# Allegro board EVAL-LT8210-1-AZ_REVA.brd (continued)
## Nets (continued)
UNNAMED_3_ADLT82101_I10_IMON: CIMON3.1 IMON3.1(N1) R28.2(N2) RIMON3.1 U3.7
UNNAMED_3_ADLT82101_I10_RT: RT3.2(N2) U3.3
UNNAMED_3_ADLT82101_I10_SNSN1: C63.2(N2) R24.2(N2) U3.30
UNNAMED_3_ADLT82101_I10_SNSP1: C63.1 R23.2(N2) U3.31
UNNAMED_3_ADLT82101_I10_SS: CSS3.2(N2) U3.6
UNNAMED_3_ADLT82101_I10_SW1: CBST5.1 MA5.1 MA5.2 MA5.3(S3) MA6.1 MA6.2 MA6.3(S3) MB5.5 MB5.6 MB5.7 MB5.8 MB6.5 MB6.6 MB6.7 MB6.8 RSNS7.4(N4) RSNS7_1.4(N4) U3.28
UNNAMED_3_ADLT82101_I10_SW2: CBST6.2(N2) L3.2(N2) L3B.1(N1) MC5.5 MC5.6 MC5.7 MC5.8 MC6.5 MC6.6 MC6.7 MC6.8 MD5.1 MD5.2 MD5.3(S3) MD6.1 MD6.2 MD6.3(S3) U3.19
UNNAMED_3_ADLT82101_I10_TG1: MA5.4 MA6.4 TPA3.1(N1) U3.29
UNNAMED_3_ADLT82101_I10_TG2: MD5.4 MD6.4 TPD3.1(N1) U3.18
UNNAMED_3_ADLT82101_I10_VC1: CP5.2(N2) R29.2(N2) RC7.2(N2) RC9.1 U3.8
UNNAMED_3_ADLT82101_I10_VC2: CP6.2(N2) R30.1 RC8.2(N2) RC9.2(N2) U3.9
UNNAMED_3_ADLT82101_I10_VDD: CVDD3.2(N2) D5.A(P) U3.5
UNNAMED_3_ADLT82101_I10_VIN: C53.2(N2) RIN3.1 U3.35
UNNAMED_3_ADLT82101_I10_VINP: C54.2(N2) R22.1 U3.33
UNNAMED_3_ADLT82101_I10_VOUT: CFOUT3.1 ROUT3.1 U3.13(VOUT)
UNNAMED_3_CAP_I22_N1: C49.1 MDG5.4 MDG6.4 R21.1
UNNAMED_3_CAP_I128_N2: C64.2(N2) C65.2(N2) C66.2(N2) C67.2(N2) C68.2(N2) C69.2(N2) C70.P C70_1.P MD5.5 MD5.6 MD5.7 MD5.8 MD6.5 MD6.6 MD6.7 MD6.8 R26.2(N2) R66.1 ROUT3.2(N2) RSNS8.3 RSNS8.4(N4) RSNS8_1.3 RSNS8_1.4(N4)
UNNAMED_3_CAP_I151_N2: CC5.2(N2) RC7.1
UNNAMED_3_CAP_I154_N2: CC6.2(N2) RC8.1
UNNAMED_3_CAPP_I25_N1: C50.P C51.P C51_1.P C52.P C52_1.P C55.P C56.2(N2) C57.2(N2) C58.2(N2) C59.2(N2) C60.2(N2) C61.2(N2) C62.2(N2) MA5.5 MA5.6 MA5.7 MA5.8 MA6.5 MA6.6 MA6.7 MA6.8 MDG5.5 MDG5.6 MDG5.7 MDG5.8 MDG6.5 MDG6.6 MDG6.7 MDG6.8 R22.2(N2) RSNS9.2 RSNS9.4(N4) RSNS9_1.2 RSNS9_1.4(N4)
UNNAMED_3_DIOLED_I1_P: DS3.A(P) RPWGD3.1
UNNAMED_3_IND_I87_N1: L3.1 L3A.1(N1) RSNS7.2 RSNS7_1.2
UNNAMED_3_NCTESTPAD_I76_N1: MB5.4 MB6.4 RBG5.1 TPB3.1(N1)
UNNAMED_3_NCTESTPAD_I88_N1: MC5.4 MC6.4 RBG6.1 TPC3.1(N1)
UNNAMED_3_RES_I33_N2: RSNPA3.2(N2) RSNS9.3 RSNS9_1.3
UNNAMED_3_RES_I37_N2: RSNPB3.2(N2) RSNS9.1 RSNS9_1.1
UNNAMED_3_RES_I78_N1: R23.1 RSNS7.3 RSNS7_1.3
UNNAMED_3_RES_I84_N1: R24.1 RSNS7.1 RSNS7_1.1
UNNAMED_3_RES_I117_N1: R1A3.1 R1C3.1 R59.1
UNNAMED_3_RES_I120_N1: R2A3.1 R2C3.1 R60.1
UNNAMED_4_ADLT82101_I10_BG1: RBG7.2(N2) U4.23
UNNAMED_4_ADLT82101_I10_BG2: RBG8.2(N2) U4.21
UNNAMED_4_ADLT82101_I10_BST1: RBST7.2(N2) U4.27
UNNAMED_4_ADLT82101_I10_BST2: RBST8.2(N2) U4.20
UNNAMED_4_ADLT82101_I10_DG: DG4.1(N1) R31.2(N2) U4.34
UNNAMED_4_ADLT82101_I10_FB1: R1A4.2(N2) R1B4.1 R3C4.1 U4.11
UNNAMED_4_ADLT82101_I10_FB2: R2A4.2(N2) R2B4.2(N2) R3C4.2(N2) U4.10
UNNAMED_4_ADLT82101_I10_GATEVCC: CGATE4.1 DBST7.A(P) DBST8.A(P) U4.24
UNNAMED_4_ADLT82101_I10_IMON: CIMON4.1 IMON4.1(N1) R38.2(N2) RIMON4.1 U4.7
UNNAMED_4_ADLT82101_I10_RT: RT4.2(N2) U4.3
UNNAMED_4_ADLT82101_I10_SNSN1: C87.2(N2) R34.2(N2) U4.30
UNNAMED_4_ADLT82101_I10_SNSP1: C87.1 R33.2(N2) U4.31
UNNAMED_4_ADLT82101_I10_SS: CSS4.2(N2) U4.6
UNNAMED_4_ADLT82101_I10_SW1: CBST7.1 MA7.1 MA7.2 MA7.3(S3) MA8.1 MA8.2 MA8.3(S3) MB7.5 MB7.6 MB7.7 MB7.8 MB8.5 MB8.6 MB8.7 MB8.8 RSNS10.4(N4) RSNS10_1.4(N4) U4.28
UNNAMED_4_ADLT82101_I10_SW2: CBST8.2(N2) L4.2(N2) L4B.1(N1) MC7.5 MC7.6 MC7.7 MC7.8 MC8.5 MC8.6 MC8.7 MC8.8 MD7.1 MD7.2 MD7.3(S3) MD8.1 MD8.2 MD8.3(S3) U4.19
UNNAMED_4_ADLT82101_I10_TG1: MA7.4 MA8.4 TPA4.1(N1) U4.29
UNNAMED_4_ADLT82101_I10_TG2: MD7.4 MD8.4 TPD4.1(N1) U4.18
UNNAMED_4_ADLT82101_I10_VC1: CP7.2(N2) R39.2(N2) RC10.2(N2) RC12.1 U4.8
UNNAMED_4_ADLT82101_I10_VC2: CP8.2(N2) R40.1 RC11.2(N2) RC12.2(N2) U4.9
UNNAMED_4_ADLT82101_I10_VDD: CVDD4.2(N2) D7.A(P) U4.5
UNNAMED_4_ADLT82101_I10_VIN: C77.2(N2) RIN4.1 U4.35
UNNAMED_4_ADLT82101_I10_VINP: C78.2(N2) R32.1 U4.33
UNNAMED_4_ADLT82101_I10_VOUT: CFOUT4.1 ROUT4.1 U4.13(VOUT)
UNNAMED_4_CAP_I22_N1: C73.1 MDG7.4 MDG8.4 R31.1
UNNAMED_4_CAP_I128_N2: C88.2(N2) C89.2(N2) C90.2(N2) C91.2(N2) C92.2(N2) C93.2(N2) C94.P C94_1.P MD7.5 MD7.6 MD7.7 MD7.8 MD8.5 MD8.6 MD8.7 MD8.8 R36.2(N2) R67.1 ROUT4.2(N2) RSNS11.3 RSNS11.4(N4) RSNS11_1.3 RSNS11_1.4(N4)
UNNAMED_4_CAP_I151_N2: CC7.2(N2) RC10.1
UNNAMED_4_CAP_I154_N2: CC8.2(N2) RC11.1
UNNAMED_4_CAPP_I25_N1: C74.P C75.P C75_1.P C76.P C76_1.P C79.P C80.2(N2) C81.2(N2) C82.2(N2) C83.2(N2) C84.2(N2) C85.2(N2) C86.2(N2) MA7.5 MA7.6 MA7.7 MA7.8 MA8.5 MA8.6 MA8.7 MA8.8 MDG7.5 MDG7.6 MDG7.7 MDG7.8 MDG8.5 MDG8.6 MDG8.7 MDG8.8 R32.2(N2) RSNS12.2 RSNS12.4(N4) RSNS12_1.2 RSNS12_1.4(N4)
UNNAMED_4_DIOLED_I1_P: DS4.A(P) RPWGD4.1
UNNAMED_4_IND_I87_N1: L4.1 L4A.1(N1) RSNS10.2 RSNS10_1.2
UNNAMED_4_NCTESTPAD_I76_N1: MB7.4 MB8.4 RBG7.1 TPB4.1(N1)
UNNAMED_4_NCTESTPAD_I88_N1: MC7.4 MC8.4 RBG8.1 TPC4.1(N1)
UNNAMED_4_RES_I33_N2: RSNPA4.2(N2) RSNS12.3 RSNS12_1.3
UNNAMED_4_RES_I37_N2: RSNPB4.2(N2) RSNS12.1 RSNS12_1.1
UNNAMED_4_RES_I78_N1: R33.1 RSNS10.3 RSNS10_1.3
UNNAMED_4_RES_I84_N1: R34.1 RSNS10.1 RSNS10_1.1
UNNAMED_4_RES_I117_N1: R1A4.1 R1C4.1 R61.1
UNNAMED_4_RES_I120_N1: R2A4.1 R2C4.1 R62.1
UNNAMED_5_ADLT8631_I47_BST: C104.2(N2) U6.18
UNNAMED_5_ADLT8631_I47_EN: R46.2(N2) R47.1 U6.3
UNNAMED_5_ADLT8631_I47_FB: C105.2(N2) R49.2(N2) R50.1 U6.11
UNNAMED_5_ADLT8631_I47_IND: L6.1 U6.14
UNNAMED_5_ADLT8631_I47_INTVCC: C106.1 U6.16
UNNAMED_5_ADLT8631_I47_RT: R48.1 U6.8
UNNAMED_5_ADLT8631_I47_SW: C104.1 D9.C L6.2(N2) U6.20
UNNAMED_5_ADLT8631_I47_TR: C103.1 U6.10
UNNAMED_5_ADLT8631_I47_VIN: C98.P C100.1 C102.2(N2) L5.2(N2) R46.1 U6.1
UNNAMED_5_ADLT8631_I47_VOUT: C105.1 C107.1 C108.1 R49.1 R51.1 R52.1 R53.1 R54.1 U6.12(VOUT)
UNNAMED_5_ADLT8631_I98_BST: C120.2(N2) U7.18
UNNAMED_5_ADLT8631_I98_EN: R69.2(N2) R70.1 U7.3
UNNAMED_5_ADLT8631_I98_FB: C121.2(N2) R78.2(N2) R79.1 U7.11
UNNAMED_5_ADLT8631_I98_IND: L7.1 U7.14
UNNAMED_5_ADLT8631_I98_INTVCC: C122.1 U7.16
UNNAMED_5_ADLT8631_I98_RT: R71.1 U7.8
UNNAMED_5_ADLT8631_I98_SW: C120.1 D4.C L7.2(N2) U7.20
UNNAMED_5_ADLT8631_I98_TR: C118.1 U7.10
UNNAMED_5_ADLT8631_I98_VOUT: C119.1 C121.1 C123.1 C124.1 R75.1 R78.1 U7.12(VOUT) U8.4
UNNAMED_5_ADLTC2052X_I74_: R73.2(N2) R74.1 R77.1 U8.3
UNNAMED_5_ADLTC2052X_I74__1: R75.2(N2) R76.1 U8.2
UNNAMED_5_ADLTC2052X_I82_: U8.13 U8.14
UNNAMED_5_ADLTC2052X_I83_: U8.8 U8.9
UNNAMED_5_ADLTC2052X_I92_: U8.6 U8.7
UNNAMED_5_DIOMMBZ5221_I58_N: D2.3 R72.2(N2) R73.1
UNNAMED_7_ADLT82101_I136_BG1: RBG3.2(N2) U2.23
UNNAMED_7_ADLT82101_I136_BG2: RBG4.2(N2) U2.21
UNNAMED_7_ADLT82101_I136_BST1: RBST3.2(N2) U2.27
UNNAMED_7_ADLT82101_I136_BST2: RBST4.2(N2) U2.20
UNNAMED_7_ADLT82101_I136_DG: DG2.1(N1) R11.2(N2) U2.34
UNNAMED_7_ADLT82101_I136_FB1: R1A2.2(N2) R1B2.1 R3C2.1 U2.11
UNNAMED_7_ADLT82101_I136_FB2: R2A2.2(N2) R2B2.2(N2) R3C2.2(N2) U2.10
UNNAMED_7_ADLT82101_I136_GATEVCC: CGATE2.1 DBST3.A(P) DBST4.A(P) U2.24
UNNAMED_7_ADLT82101_I136_IMON: CIMON2.1 IMON2.1(N1) R18.2(N2) RIMON2.1 U2.7
UNNAMED_7_ADLT82101_I136_RT: RT2.2(N2) U2.3
UNNAMED_7_ADLT82101_I136_SNSN1: C39.2(N2) R14.2(N2) U2.30
UNNAMED_7_ADLT82101_I136_SNSP1: C39.1 R13.2(N2) U2.31
UNNAMED_7_ADLT82101_I136_SS: CSS2.2(N2) U2.6
UNNAMED_7_ADLT82101_I136_SW1: CBST3.1 MA3.1 MA3.2 MA3.3(S3) MA4.1 MA4.2 MA4.3(S3) MB3.5 MB3.6 MB3.7 MB3.8 MB4.5 MB4.6 MB4.7 MB4.8 RSNS4.4(N4) RSNS4_1.4(N4) U2.28
UNNAMED_7_ADLT82101_I136_SW2: CBST4.2(N2) L2.2(N2) L2B.1(N1) MC3.5 MC3.6 MC3.7 MC3.8 MC4.5 MC4.6 MC4.7 MC4.8 MD3.1 MD3.2 MD3.3(S3) MD4.1 MD4.2 MD4.3(S3) U2.19
UNNAMED_7_ADLT82101_I136_TG1: MA3.4 MA4.4 TPA2.1(N1) U2.29
UNNAMED_7_ADLT82101_I136_TG2: MD3.4 MD4.4 TPD2.1(N1) U2.18
UNNAMED_7_ADLT82101_I136_VC1: CP3.2(N2) R19.2(N2) RC4.2(N2) RC6.1 U2.8
UNNAMED_7_ADLT82101_I136_VC2: CP4.2(N2) R20.1 RC5.2(N2) RC6.2(N2) U2.9
UNNAMED_7_ADLT82101_I136_VDD: CVDD2.2(N2) D3.A(P) U2.5
UNNAMED_7_ADLT82101_I136_VIN: C29.2(N2) RIN2.1 U2.35
UNNAMED_7_ADLT82101_I136_VINP: C30.2(N2) R12.1 U2.33
UNNAMED_7_ADLT82101_I136_VOUT: CFOUT2.1 ROUT2.1 U2.13(VOUT)
UNNAMED_7_CAP_I21_N1: C25.1 MDG3.4 MDG4.4 R11.1
UNNAMED_7_CAP_I127_N2: C40.2(N2) C41.2(N2) C42.2(N2) C43.2(N2) C44.2(N2) C45.2(N2) C46.P C46_1.P MD3.5 MD3.6 MD3.7 MD3.8 MD4.5 MD4.6 MD4.7 MD4.8 R16.2(N2) R68.1 ROUT2.2(N2) RSNS5.3 RSNS5.4(N4) RSNS5_1.3 RSNS5_1.4(N4)
UNNAMED_7_CAP_I151_N2: CC3.2(N2) RC4.1
UNNAMED_7_CAP_I154_N2: CC4.2(N2) RC5.1
UNNAMED_7_CAPP_I24_N1: C26.P C27.P C27_1.P C28.P C28_1.P C31.P C32.2(N2) C33.2(N2) C34.2(N2) C35.2(N2) C36.2(N2) C37.2(N2) C38.2(N2) MA3.5 MA3.6 MA3.7 MA3.8 MA4.5 MA4.6 MA4.7 MA4.8 MDG3.5 MDG3.6 MDG3.7 MDG3.8 MDG4.5 MDG4.6 MDG4.7 MDG4.8 R12.2(N2) RSNS6.2 RSNS6.4(N4) RSNS6_1.2 RSNS6_1.4(N4)
UNNAMED_7_DIOLED_I1_P: DS2.A(P) RPWGD2.1
UNNAMED_7_IND_I86_N1: L2.1 L2A.1(N1) RSNS4.2 RSNS4_1.2
UNNAMED_7_NCTESTPAD_I75_N1: MB3.4 MB4.4 RBG3.1 TPB2.1(N1)
UNNAMED_7_NCTESTPAD_I87_N1: MC3.4 MC4.4 RBG4.1 TPC2.1(N1)
UNNAMED_7_RES_I32_N2: RSNPA2.2(N2) RSNS6.3 RSNS6_1.3
UNNAMED_7_RES_I36_N2: RSNPB2.2(N2) RSNS6.1 RSNS6_1.1
UNNAMED_7_RES_I77_N1: R13.1 RSNS4.3 RSNS4_1.3
UNNAMED_7_RES_I83_N1: R14.1 RSNS4.1 RSNS4_1.1
UNNAMED_7_RES_I116_N1: R1A2.1 R1C2.1 R63.1
UNNAMED_7_RES_I119_N1: R2A2.1 R2C2.1 R64.1
VC1: R9.1 R19.1 R29.1 R39.1
VC2: R10.2(N2) R20.2(N2) R30.2(N2) R40.2(N2)
VOUT: C23.P C23_1.P C47.P C47_1.P C71.P C71_1.P C95.P C95_1.P C109.2(N2) C110.2(N2) C111.2(N2) C112.2(N2) C113.2(N2) C114.2(N2) C115.2(N2) C116.2(N2) E4.1(N1) P7.1(N1) P8.1(N1) R1C1.2(N2) R1C2.2(N2) R1C3.2(N2) R1C4.2(N2) R2C1.2(N2) R2C2.2(N2) R2C3.2(N2) R2C4.2(N2) R5.1 R7.2(N2) R15.1 R17.2(N2) R25.1 R27.2(N2) R35.1 R37.2(N2) R57.1 R58.1 R65.2(N2) R66.2(N2) R67.2(N2) R68.2(N2) RSNS2.1 RSNS2.2 RSNS2_1.1 RSNS2_1.2 RSNS5.1 RSNS5.2 RSNS5_1.1 RSNS5_1.2 RSNS8.1 RSNS8.2 RSNS8_1.1 RSNS8_1.2 RSNS11.1 RSNS11.2 RSNS11_1.1 RSNS11_1.2

Pads without a net: D2 2; U1 12 14 17 26 32 36 38; U2 12 14 17 26 32 36 38; U3 12 14 17 26 32 36 38; U4 12 14 17 26 32 36 38; U5 2; U6 5 6 9 13 15; U7 5 6 9 13 15

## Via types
v1: diameter 0.508, hole 0.254, TOP to BOTTOM, 228 vias
v2: diameter 0.61, hole 0.305, TOP to BOTTOM, 6707 vias
v3: diameter 0.61, hole 0.254, TOP to BOTTOM, 100 vias

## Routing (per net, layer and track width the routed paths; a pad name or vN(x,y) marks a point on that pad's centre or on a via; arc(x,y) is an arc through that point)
GND_POWER: length 32.2
  TOP w0.203: C2.N v2(47.5,33.15)
  TOP w0.254: U4.4 113.43,285.62 v1(113.26,285.44) ; v1(113.26,195.66) 113.43,195.83 U3.4 ; U2.4 113.44,106.04 v1(113.26,105.87) ; v1(113.26,18.62) 113.43,18.79 U1.4
  TOP w0.279: RIMON1.2 110.39,12.66 CIMON1.2 111.8,12.6 111.8,9.98 ; U4.22 115.93,294.08 v2(116.64,294.78) ; v2(116.64,115.2) 115.94,114.5 U2.22 ; v2(116.64,204.99) 115.93,204.29 U3.22 ; 111.8,276.81 111.8,279.43 CIMON4.2 110.39,279.49 RIMON4.2 ; 107.75,277.91 107.91,277.75 ; v2(116.64,27.95) 115.93,27.25 U1.22
  TOP w0.305: C106.2 84.07,101.93 83.64,102.36 v1(83.57,102.36)
  TOP w0.381: U7.7 78.83,175.81 v2(78.61,176.02) v2(77.85,176.78)
  vias: v1(49.2,280.81) v1(78.38,284.63) v1(83.85,284.63) v1(100.08,100.2) v1(102.32,282.03) v1(102.32,192.24) v1(102.32,15.2) v1(107.72,15.75) v2(7.44,197.36) v2(7.43,174.43) v2(7.87,199.81) v2(7.87,194.91) v2(7.86,176.88) v2(7.86,171.98) v2(9.12,201.96) v2(9.12,192.75) v2(9.11,179.04) v2(9.11,169.83) v2(11.02,203.56) v2(11.02,191.15) v2(11.01,180.64) v2(11.01,168.23) v2(13.13,160.15) v2(13.11,157.1) v2(13.36,204.41) v2(13.36,190.3) v2(13.35,181.49) v2(13.35,167.38) v2(14.17,160.15) v2(14.15,157.1) v2(15.19,160.15) v2(15.16,157.1) v2(15.85,204.41) v2(15.85,190.3) v2(15.84,181.49) v2(15.84,167.38) v2(16.28,160.15) v2(16.26,157.1) v2(18.19,203.56) v2(18.19,191.15) v2(18.17,180.64) v2(18.17,168.23) v2(20.09,201.96) v2(20.09,192.75) v2(20.08,179.04) v2(20.08,169.83) v2(21.34,199.81) v2(21.34,194.91) v2(21.32,176.88) v2(21.32,171.98) v2(21.77,197.36) v2(21.76,174.43) v2(32.98,354.45) v2(32.98,351.91) v2(32.98,349.37) v2(32.98,346.83) v2(32.98,344.29) v2(32.93,38.72) v2(33.13,304.06) v2(33.13,298.98) v2(33.13,296.44) v2(33.13,293.9) v2(33.13,291.36) v2(33.13,288.82) v2(33.13,276.12) v2(33.13,273.58) v2(33.13,271.04) v2(33.13,265.96) v2(33.13,263.42) v2(33.13,260.88) v2(33.13,258.34) v2(33.13,255.8) v2(33.13,253.26) v2(33.15,217.81) v2(33.13,214.27) v2(33.13,209.19) v2(33.13,206.65) v2(33.13,204.11) v2(33.13,201.57) v2(33.13,199.03) v2(33.13,196.49) v2(33.13,193.95) v2(33.13,191.41) v2(33.13,188.87) v2(33.13,186.33) v2(33.13,183.79) v2(33.13,181.25) v2(33.13,171.09) v2(33.13,168.55) v2(33.13,166.01) v2(33.13,163.47) v2(33.13,124.48) v2(33.13,119.4) v2(33.13,116.86) v2(33.13,114.32) v2(33.13,111.78) v2(33.13,109.24) v2(33.13,106.7) v2(33.13,104.16) v2(33.13,101.62) v2(33.13,99.08) v2(33.13,96.54) v2(33.13,94) v2(33.13,86.38) v2(33.13,83.84) v2(33.13,81.3) v2(33.13,78.76) v2(33.13,76.22) v2(33.13,35.56) v2(33.13,33.02) v2(33.13,30.48) v2(33.13,27.94) v2(33.13,25.4) v2(33.13,22.86) v2(33.13,20.32) v2(33.13,17.78) v2(33.13,15.24) v2(33.13,12.7) v2(33.13,10.16) v2(33.13,7.62) v2(33.13,5.08) v2(34.16,171.7) v2(34.29,82.42) v2(34.32,356.23) v2(34.46,342.82) v2(34.8,351.79) v2(34.8,346.71) v2(34.8,86.11) v2(35.18,297.56) v2(35.18,272.16) v2(35.18,262) v2(35.18,256.92) v2(35.17,217.93) v2(35.18,212.85) v2(35.18,207.77) v2(35.18,202.69) v2(35.18,197.61) v2(35.18,192.53) v2(35.18,187.45) v2(35.18,182.37) v2(35.18,167.13) v2(35.18,120.52) v2(35.18,119) v2(35.18,115.44) v2(35.18,110.36) v2(35.17,40.83) v2(35.18,35.56) v2(35.18,30.48) v2(35.18,25.4) v2(35.18,20.32) v2(35.18,15.24) v2(35.18,10.16) v2(35.18,5.08) v2(35.18,2.92) v2(35.31,195.12) v2(35.38,163.25) v2(35.41,253.05) v2(35.4,76.01) v2(35.59,190.12) v2(36.52,216.61) v2(36.53,208.99) v2(36.53,203.91) v2(36.53,198.83) v2(36.86,356.23) v2(37,342.82) v2(37.34,354.33) v2(37.35,215.44) v2(37.34,125.73) v2(37.69,163.32) v2(37.71,307.72) v2(37.72,300.1) v2(37.72,295.02) v2(37.72,270) v2(37.72,264.92) v2(37.72,184.91) v2(37.72,179.83) v2(37.72,117.98) v2(37.72,112.9) v2(37.72,107.82) v2(37.71,40.83) v2(37.72,35.56) v2(37.72,33.02) v2(37.72,27.94) v2(37.72,22.86) v2(37.72,17.78) v2(37.72,12.7) v2(37.72,7.62) v2(37.72,2.92) v2(37.92,347.34) v2(37.92,256.92) v2(37.92,168.97) v2(37.93,81.72) v2(39.17,285.24) v2(39.4,356.23) v2(39.45,283.03) v2(39.54,342.82) v2(39.62,346.71) v2(39.8,266.18) v2(39.78,253.42) v2(39.78,217.67) v2(39.8,215.36) v2(39.8,212.74) v2(39.79,210.43) v2(39.8,191.51) v2(39.78,100.85) v2(39.88,351.79) v2(39.81,268.98) v2(39.83,179.18) v2(39.81,167.12) v2(39.83,125.09) v2(39.83,120.52) v2(40.14,40.86) v2(40.25,307.72) v2(40.26,297.56) v2(40.26,10.16) v2(40.26,5.08) v2(40.26,2.92) v2(41.73,283.08) v2(41.71,256.13) v2(41.73,253.05) v2(41.78,86.74) v2(41.83,261.26) v2(41.94,356.23) v2(41.91,84.96) v2(41.91,79.88) v2(42.08,342.82) v2(42.42,354.33) v2(42.42,349.25) v2(42.42,344.17) v2(42.79,307.72) v2(42.8,305.18) v2(42.8,295.02) v2(42.8,7.62) v2(42.8,2.92) v2(43.57,40.82) v2(43.82,171.58) v2(43.95,274.96) v2(43.95,270.84) v2(43.95,264.31) v2(44.48,356.23) v2(44.62,342.82) v2(44.96,351.79) v2(44.96,346.71) v2(45.33,307.72) v2(45.34,302.64) v2(45.34,297.56) v2(45.34,262) v2(45.34,256.92) v2(45.33,217.93) v2(45.34,207.77) v2(45.34,202.69) v2(45.34,197.61) v2(45.34,187.45) v2(45.34,182.37) v2(45.34,167.13) v2(45.34,125.6) v2(45.34,115.95) v2(45.34,110.36) v2(45.34,95.12) v2(45.34,5.08) v2(45.34,2.92) v2(45.42,253.06) v2(45.43,163.26) v2(45.44,76.01) v2(46.96,304.24) v2(46.99,84.96) v2(46.99,79.88) v2(47.02,356.23) v2(47.16,342.82) v2(47.5,354.33) v2(47.5,349.25) v2(47.5,344.17) v2(47.5,213.74) v2(47.53,123.08) v2(47.54,40.82) v2(47.62,86.11) v2(47.87,307.72) v2(47.88,295.02) v2(47.88,205.61) v2(47.88,184.91) v2(47.88,179.83) v2(47.88,169.67) v2(47.88,163.2) v2(47.88,117.98) v2(47.88,103) v2(47.88,97.66) v2(47.88,2.92) v2(48.39,171.58) v2(49.15,212.85) v2(49.4,262) v2(49.4,257.05) v2(49.42,253.05) v2(49.4,207.52) v2(49.4,187.45) v2(49.4,182.37) v2(49.4,125.6) v2(49.4,115.95) v2(49.56,356.23) v2(49.53,217.82) v2(49.53,167.26) v2(49.53,82.42) v2(49.53,77.34) v2(49.7,342.82) v2(50.04,351.79) v2(50.04,346.71) v2(50.01,25.3) v2(50.41,307.72) v2(50.42,302.64) v2(50.42,297.56) v2(50.42,2.92) v2(50.9,95.22) v2(50.9,40.83) v2(51.94,25.6) v2(52.1,356.23) v2(52.24,342.82) v2(52.58,354.33) v2(52.58,349.25) v2(52.58,344.17) v2(52.95,307.72) v2(52.96,305.18) v2(52.96,295.02) v2(52.96,269.62) v2(52.96,205.23) v2(52.96,200.15) v2(52.96,2.92) v2(53.19,253.05) v2(53.34,103) v2(53.59,217.68) v2(53.59,215.39) v2(53.72,164.34) v2(53.98,122.94) v2(54.1,185.04) v2(54.1,179.96) v2(54.1,79.76) v2(54.36,117.86) v2(54.36,112.78) v2(54.36,107.7) v2(54.48,264.54) v2(54.64,356.23) v2(54.78,342.82) v2(54.74,86.49) v2(55.42,308.31) v2(55.5,302.64) v2(55.5,297.56) v2(55.42,218.52) v2(55.5,212.85) v2(55.5,207.77) v2(55.5,202.69) v2(55.5,197.61) v2(55.5,130.68) v2(55.42,128.73) v2(55.5,125.6) v2(55.5,115.95) v2(55.5,110.36) v2(55.5,95.12) v2(55.42,41.48) v2(55.5,40.64) v2(55.5,35.56) v2(55.5,15.24) v2(55.5,10.16) v2(55.5,2.92) v2(55.72,76.01) v2(55.8,347.28) v2(55.8,256.8) v2(55.8,168.84) v2(55.8,81.59) v2(57.18,356.23) v2(57.32,342.82) v2(57.66,354.33) v2(57.66,349.25) v2(57.66,344.17) v2(58.04,310.26) v2(58.04,305.18) v2(58.04,295.02) v2(58.04,269.62) v2(58.04,264.54) v2(58.04,259.46) v2(58.04,254.38) v2(58.04,220.47) v2(58.04,215.39) v2(58.04,205.23) v2(58.04,200.15) v2(58.04,184.91) v2(58.04,179.83) v2(58.04,169.67) v2(58.04,164.59) v2(58.04,128.14) v2(58.04,123.06) v2(58.04,117.98) v2(58.04,112.9) v2(58.04,107.82) v2(58.04,97.66) v2(58.04,43.18) v2(58.04,33.02) v2(58.04,27.94) v2(58.04,2.92) v2(58.17,103) v2(58.27,253.05) v2(58.25,163.27) v2(58.26,76.01) v2(59.31,93.73) v2(59.56,171.7) v2(59.69,82.42) v2(59.72,356.23) v2(59.86,342.82) v2(60.2,351.79) v2(60.2,346.71) v2(60.19,340.12) v2(60.19,337.58) v2(60.19,335.04) v2(60.19,332.5) v2(60.19,329.96) v2(60.33,251.16) v2(60.33,248.62) v2(60.33,246.08) v2(60.33,243.54) v2(60.33,241) v2(60.31,161.37) v2(60.31,158.83) v2(60.31,156.29) v2(60.31,153.75) v2(60.31,151.21) v2(60.31,74.12) v2(60.31,71.58) v2(60.31,69.04) v2(60.31,66.5) v2(60.31,63.96) v2(60.58,302.64) v2(60.58,297.56) v2(60.58,272.16) v2(60.58,262) v2(60.58,256.92) v2(60.58,212.85) v2(60.58,207.77) v2(60.58,202.69) v2(60.58,197.61) v2(60.58,187.45) v2(60.58,182.37) v2(60.58,167.13) v2(60.58,115.95) v2(60.58,110.36) v2(60.58,35.56) v2(60.58,30.48) v2(60.58,25.4) v2(60.58,20.32) v2(60.58,10.16) v2(60.58,2.92) v2(60.71,86.36) v2(62.19,149.91) v2(62.26,356.23) v2(62.24,239.76) v2(62.23,79.88) v2(62.23,74.8) v2(62.23,69.72) v2(62.22,62.66) v2(62.62,329.64) v2(62.74,354.33) v2(62.74,349.25) v2(62.74,344.17) v2(62.74,339.09) v2(62.74,334.01) v2(63.12,310.26) v2(63.12,305.18) v2(63.12,295.02) v2(63.12,289.94) v2(63.12,274.7) v2(63.12,269.62) v2(63.12,264.54) v2(63.12,259.46) v2(63.12,254.38) v2(63.12,249.3) v2(63.12,244.22) v2(63.12,220.47) v2(63.12,215.39) v2(63.12,205.23) v2(63.12,200.15) v2(63.12,184.91) v2(63.12,179.83) v2(63.12,169.67) v2(63.12,164.59) v2(63.12,159.51) v2(63.12,154.43) v2(63.12,128.14) v2(63.12,117.98) v2(63.12,112.9) v2(63.12,43.18) v2(63.12,33.02) v2(63.12,27.94) v2(63.12,22.86) v2(63.12,17.78) v2(63.12,2.92) v2(64.64,171.7) v2(64.8,356.23) v2(64.78,239.76) v2(64.73,149.91) v2(64.77,82.42) v2(64.77,77.34) v2(64.77,72.26) v2(64.77,67.18) v2(64.76,62.66) v2(65.16,329.64) v2(65.28,351.79) v2(65.28,346.71) v2(65.28,341.63) v2(65.28,336.55) v2(65.66,307.72) v2(65.66,302.64) v2(65.66,297.56) v2(65.66,292.48) v2(65.66,287.4) v2(65.66,282.32) v2(65.66,277.24) v2(65.66,272.16) v2(65.66,262) v2(65.66,256.92) v2(65.66,251.84) v2(65.66,246.76) v2(65.66,217.93) v2(65.66,212.85) v2(65.66,207.77) v2(65.66,202.69) v2(65.66,197.61) v2(65.66,187.45) v2(65.66,182.37) v2(65.66,167.13) v2(65.66,162.05) v2(65.66,156.97) v2(65.66,125.6) v2(65.66,115.95) v2(65.66,110.36) v2(65.66,40.64) v2(65.66,35.56) v2(65.66,30.48) v2(65.66,25.4) v2(65.66,20.32) v2(65.66,15.24) v2(65.66,10.16) v2(65.66,2.92) v2(65.79,130.18) v2(66.18,331.3) v2(66.17,154.69) v2(66.18,151.73) v2(66.18,64.48) v2(66.42,164.72) v2(66.42,159.64) v2(66.42,149.86) v2(66.55,215.9) v2(67.3,62.66) v2(67.34,356.23) v2(67.31,79.88) v2(67.31,74.8) v2(67.31,69.72) v2(67.7,329.64) v2(67.82,354.33) v2(67.82,349.25) v2(67.82,344.17) v2(67.82,339.09) v2(67.82,334.01) v2(67.82,239.65) v2(68.2,310.26) v2(68.2,305.18) v2(68.2,295.02) v2(68.2,289.94) v2(68.2,274.7) v2(68.2,269.62) v2(68.2,264.54) v2(68.2,259.46) v2(68.2,254.38) v2(68.2,249.3) v2(68.2,244.22) v2(68.2,205.23) v2(68.2,200.15) v2(68.2,123.06) v2(68.2,112.9) v2(68.2,45.47) v2(68.2,43.18) v2(68.2,33.02) v2(68.2,27.94) v2(68.2,22.86) v2(68.2,17.78) v2(68.2,2.92) v2(68.71,312.31) v2(69.22,126.75) v2(69.47,222.63) v2(69.6,131.7) v2(69.66,163.64) v2(69.72,220.22) v2(69.88,356.23) v2(69.85,82.42) v2(70.36,351.79) v2(70.69,132.77) v2(70.74,307.72) v2(70.74,302.64) v2(70.74,297.56) v2(70.74,292.48) v2(70.74,287.4) v2(70.74,282.32) v2(70.74,277.24) v2(70.74,272.16) v2(70.74,262) v2(70.74,217.93) v2(70.74,212.85) v2(70.74,207.77) v2(70.74,202.69) v2(70.74,197.61) v2(70.74,130.68) v2(70.74,125.6) v2(70.74,110.36) v2(70.74,45.47) v2(70.74,40.64) v2(70.74,35.56) v2(70.74,30.48) v2(70.74,25.4) v2(70.74,20.32) v2(70.74,15.24) v2(70.74,10.16) v2(70.74,2.92) v2(70.99,345.44) v2(70.99,344.3) v2(70.99,255.65) v2(70.99,254.51) v2(70.94,253.43) v2(70.99,179.58) v2(70.99,165.86) v2(70.99,164.72) v2(70.99,163.65) v2(70.99,78.61) v2(70.99,77.47) v2(70.99,76.5) v2(71.01,343.22) v2(71.25,312.31) v2(71.28,222.63) v2(71.63,178.18) v2(72.14,345.44) v2(72.14,344.3) v2(72.14,343.15) v2(72.14,255.65) v2(72.14,254.51) v2(72.14,253.36) v2(72.14,165.86) v2(72.14,164.72) v2(72.14,163.58) v2(72.14,78.61) v2(72.14,77.47) v2(72.14,76.33) v2(72.39,79.88) v2(72.42,356.23) v2(72.77,178.18) v2(72.9,354.33) v2(72.9,349.25) v2(73.02,179.58) v2(73.15,307.97) v2(73.15,218.18) v2(73.15,128.39) v2(73.15,41.15) v2(73.28,345.44) v2(73.28,344.3) v2(73.28,343.15) v2(73.28,295.02) v2(73.28,289.94) v2(73.28,274.7) v2(73.28,269.62) v2(73.28,264.54) v2(73.28,259.46) v2(73.28,255.65) v2(73.28,254.51) v2(73.28,253.36) v2(73.28,205.23) v2(73.28,200.15) v2(73.28,165.86) v2(73.28,164.72) v2(73.28,163.58) v2(73.23,132.77) v2(73.28,123.06) v2(73.28,117.98) v2(73.28,78.61) v2(73.28,77.47) v2(73.28,76.33) v2(73.28,45.47) v2(73.28,33.02) v2(73.28,27.94) v2(73.28,22.86) v2(73.28,17.78) v2(73.28,2.92) v2(73.79,312.31) v2(73.82,222.63) v2(74.42,345.44) v2(74.42,344.3) v2(74.42,343.15) v2(74.42,255.65) v2(74.42,254.51) v2(74.42,253.36) v2(74.42,165.86) v2(74.42,164.72) v2(74.42,163.58) v2(74.42,78.61) v2(74.42,77.47) v2(74.42,76.33) v2(74.96,356.23) v2(74.93,82.42) v2(75.44,351.79) v2(75.56,345.44) v2(75.56,344.3) v2(75.56,343.15) v2(75.56,255.65) v2(75.56,254.51) v2(75.56,253.36) v2(75.57,165.86) v2(75.57,164.72) v2(75.57,163.58) v2(75.56,78.61) v2(75.56,77.47) v2(75.56,76.33) v2(75.77,132.77) v2(75.82,307.72) v2(75.82,302.64) v2(75.82,297.56) v2(75.82,292.48) v2(75.82,287.4) v2(75.82,282.32) v2(75.82,277.24) v2(75.82,272.16) v2(75.82,262) v2(75.82,217.93) v2(75.82,212.85) v2(75.82,207.77) v2(75.82,202.69) v2(75.82,197.61) v2(75.82,130.68) v2(75.82,125.6) v2(75.82,116.08) v2(75.82,45.47) v2(75.82,40.64) v2(75.82,35.56) v2(75.82,30.48) v2(75.82,25.4) v2(75.82,20.32) v2(75.82,10.16) v2(75.82,2.92) v2(76.33,312.31) v2(76.36,222.63) v2(76.33,177.55) v2(76.33,176.78) v2(76.33,176.02) v2(76.33,169.67) v2(76.71,345.44) v2(76.71,344.3) v2(76.71,343.15) v2(76.71,255.65) v2(76.71,254.51) v2(76.71,253.36) v2(76.71,165.86) v2(76.71,164.72) v2(76.71,163.58) v2(76.71,78.61) v2(76.71,77.47) v2(76.71,76.33) v2(77.09,177.55) v2(77.09,176.78) v2(77.09,176.02) v2(77.5,356.23) v2(77.47,79.88) v2(77.72,184.4) v2(77.72,183.64) v2(77.85,345.44) v2(77.85,344.3) v2(77.85,343.15) v2(77.85,255.65) v2(77.85,254.51) v2(77.85,253.36) v2(77.85,177.55) v2(77.85,176.02) v2(77.85,169.67) v2(77.85,165.86) v2(77.85,164.72) v2(77.85,163.58) v2(77.85,78.61) v2(77.85,77.47) v2(77.85,76.33) v2(77.98,354.33) v2(77.98,349.25) v2(78.36,310.26) v2(78.36,305.18) v2(78.36,295.02) v2(78.36,289.94) v2(78.36,274.7) v2(78.36,269.62) v2(78.36,264.54) v2(78.36,259.46) v2(78.36,220.47) v2(78.36,215.39) v2(78.36,205.23) v2(78.36,200.15) v2(78.31,132.77) v2(78.36,128.14) v2(78.36,123.06) v2(78.36,117.98) v2(78.36,112.9) v2(78.36,45.47) v2(78.36,43.81) v2(78.36,33.02) v2(78.36,27.94) v2(78.36,22.86) v2(78.36,12.7) v2(78.36,2.92) v2(78.61,177.55) v2(78.61,176.78) v2(78.61,169.8) v2(78.87,312.31) v2(78.99,345.44) v2(78.99,344.3) v2(78.99,343.15) v2(78.99,255.65) v2(78.99,254.51) v2(78.99,253.36) v2(78.9,222.63) v2(78.99,165.86) v2(78.99,164.72) v2(78.99,163.58) v2(78.99,78.61) v2(78.99,77.47) v2(78.99,76.33) v2(79.3,331.3) v2(79.3,241.51) v2(79.3,64.48) v2(79.38,177.55) v2(79.38,176.78) v2(79.38,176.02) v2(79.32,151.73) v2(80.04,356.23) v2(80.01,82.42) v2(80.14,345.44) v2(80.14,344.3) v2(80.14,343.15) v2(80.14,255.65) v2(80.14,254.51) v2(80.14,253.36) v2(80.14,169.67) v2(80.14,165.86) v2(80.14,164.72) v2(80.14,163.58) v2(80.14,78.61) v2(80.14,77.47) v2(80.14,76.33) v2(80.52,351.79) v2(80.77,88.14) v2(80.77,41.78) v2(80.87,308.94) v2(80.9,302.64) v2(80.9,297.56) v2(80.9,292.48) v2(80.9,287.4) v2(80.9,282.32) v2(80.9,277.24) v2(80.9,272.16) v2(80.9,262) v2(80.87,219.15) v2(80.9,212.85) v2(80.9,207.77) v2(80.9,202.69) v2(80.9,197.61) v2(80.87,129.36) v2(80.9,125.6) v2(80.9,116.08) v2(80.9,45.47) v2(80.9,40.64) v2(80.9,35.56) v2(80.9,30.48) v2(80.9,25.4) v2(80.9,20.32) v2(80.9,15.24) v2(80.9,10.16) v2(80.9,2.92) v2(81.28,345.44) v2(81.28,344.3) v2(81.28,343.15) v2(81.28,255.65) v2(81.28,254.51) v2(81.28,253.36) v2(81.28,165.86) v2(81.28,164.72) v2(81.28,163.58) v2(81.28,78.61) v2(81.28,77.47) v2(81.28,76.33) v2(81.41,312.31) v2(81.44,222.63) v2(81.53,308.05) v2(81.53,218.26) v2(81.53,128.47) v2(81.66,88.01) v2(81.79,169.67) v2(81.91,185.93) v2(81.91,177.8) v2(81.91,41.78) v2(82.19,308.93) v2(82.19,219.14) v2(82.19,129.35) v2(82.3,96.65) v2(82.3,95.76) v2(82.3,94.87) v2(82.38,76.45) v2(82.42,345.44) v2(82.42,344.3) v2(82.42,343.22) v2(82.42,255.65) v2(82.42,254.51) v2(82.42,253.43) v2(82.42,165.86) v2(82.42,164.72) v2(82.42,163.64) v2(82.42,78.61) v2(82.42,77.47) v2(82.58,356.23) v2(82.55,79.88) v2(82.91,308.05) v2(82.91,218.26) v2(82.91,128.47) v2(83.06,354.33) v2(83.06,349.25) v2(83.06,96.65) v2(83.06,95.76) v2(83.06,94.87) v2(83.06,41.78) v2(83.39,132.77) v2(83.44,308.93) v2(83.44,305.18) v2(83.44,295.02) v2(83.44,289.94) v2(83.44,274.7) v2(83.44,269.62) v2(83.44,264.54) v2(83.44,259.46) v2(83.44,219.14) v2(83.44,215.39) v2(83.44,205.23) v2(83.44,200.15) v2(83.44,185.93) v2(83.44,177.8) v2(83.44,129.35) v2(83.44,123.06) v2(83.44,117.98) v2(83.44,112.9) v2(83.44,45.47) v2(83.44,33.02) v2(83.44,27.94) v2(83.44,22.86) v2(83.44,12.7) v2(83.44,2.92) v2(83.57,345.44) v2(83.57,344.3) v2(83.57,343.22) v2(83.57,255.65) v2(83.57,254.51) v2(83.57,253.43) v2(83.57,165.86) v2(83.57,164.72) v2(83.58,163.64) v2(83.57,91.44) v2(83.57,78.61) v2(83.57,77.47) v2(83.57,76.5) v2(83.82,310.55) v2(83.82,220.77) v2(83.82,130.98) v2(83.82,96.65) v2(83.82,95.76) v2(83.82,94.87) v2(83.82,43.73) v2(83.95,312.31) v2(83.98,222.63) v2(84.2,308.08) v2(84.2,218.29) v2(84.2,128.5) v2(84.2,41.78) v2(84.45,188.98) v2(84.58,96.65) v2(84.58,95.76) v2(84.58,94.87) v2(84.58,91.44) v2(84.71,345.44) v2(84.71,344.3) v2(84.71,343.15) v2(84.71,255.65) v2(84.71,254.51) v2(84.71,253.36) v2(84.71,165.86) v2(84.71,164.72) v2(84.71,163.58) v2(84.71,78.61) v2(84.71,77.47) v2(84.73,76.47) v2(84.81,308.93) v2(84.81,219.14) v2(84.81,129.35) v2(85.09,82.42) v2(85.12,356.23) v2(85.34,188.98) v2(85.34,96.65) v2(85.34,95.76) v2(85.34,94.87) v2(85.34,41.78) v2(85.6,351.79) v2(85.57,308.1) v2(85.57,218.31) v2(85.57,128.52) v2(85.85,345.44) v2(85.85,344.3) v2(85.85,343.15) v2(85.85,255.65) v2(85.85,254.51) v2(85.85,253.36) v2(85.85,165.86) v2(85.85,164.72) v2(85.85,163.58) v2(85.85,78.61) v2(85.85,77.47) v2(85.85,76.33) v2(85.98,302.64) v2(85.98,297.56) v2(85.98,292.48) v2(85.98,287.4) v2(85.98,282.32) v2(85.98,277.24) v2(85.98,272.16) v2(85.98,262) v2(85.98,212.85) v2(85.98,207.77) v2(85.98,202.69) v2(85.98,197.61) v2(85.93,132.77) v2(85.98,125.6) v2(85.98,116.08) v2(85.98,45.47) v2(85.98,40.64) v2(85.98,35.56) v2(85.98,30.48) v2(85.98,25.4) v2(85.98,15.24) v2(85.98,10.16) v2(85.98,2.92) v2(86.23,308.93) v2(86.23,219.14) v2(86.23,188.98) v2(86.23,129.35) v2(86.23,87) v2(86.49,312.31) v2(86.49,41.78) v2(86.52,222.63) v2(86.99,345.44) v2(86.99,344.3) v2(86.99,343.15) v2(86.99,255.65) v2(86.99,254.51) v2(86.99,253.36) v2(87,165.86) v2(87,164.72) v2(87,163.58) v2(86.99,78.61) v2(86.99,77.47) v2(86.99,76.33) v2(87.1,308.17) v2(87.1,218.38) v2(87.1,128.59) v2(87.66,356.23) v2(87.63,79.88) v2(87.63,41.78) v2(87.73,308.93) v2(87.73,219.14) v2(87.73,129.35) v2(87.88,87) v2(88.14,354.33) v2(88.14,349.25) v2(88.14,345.44) v2(88.14,344.3) v2(88.14,343.15) v2(88.14,255.65) v2(88.14,254.51) v2(88.14,253.36) v2(88.14,165.86) v2(88.14,164.72) v2(88.14,163.58) v2(88.14,78.61) v2(88.14,77.47) v2(88.14,76.33) v2(88.29,308.17) v2(88.29,218.38) v2(88.29,128.59) v2(88.47,132.77) v2(88.49,33.05) v2(88.52,305.18) v2(88.52,295.02) v2(88.52,289.94) v2(88.52,274.7) v2(88.52,269.62) v2(88.52,264.54) v2(88.52,259.46) v2(88.52,215.39) v2(88.52,205.23) v2(88.52,200.15) v2(88.52,123.06) v2(88.52,112.9) v2(88.52,45.47) v2(88.52,27.94) v2(88.52,22.86) v2(88.52,12.7) v2(88.52,2.92) v2(88.77,41.78) v2(88.93,308.93) v2(88.93,219.14) v2(88.93,129.35) v2(89.03,312.31) v2(89.06,222.63) v2(89.53,308.17) v2(89.53,218.38) v2(89.54,128.59) v2(89.92,176.28) v2(89.92,41.78) v2(90.2,356.23) v2(90.17,310.55) v2(90.17,308.93) v2(90.17,220.77) v2(90.17,219.14) v2(90.17,130.98) v2(90.17,129.35) v2(90.17,82.42) v2(90.17,77.34) v2(90.17,43.73) v2(90.55,38.35) v2(90.53,29.87) v2(90.68,351.79) v2(90.68,346.71) v2(90.76,308.17) v2(90.76,218.38) v2(90.76,128.59) v2(91.06,302.64) v2(91.06,292.48) v2(91.06,287.4) v2(91.06,277.24) v2(91.06,272.16) v2(91.06,262) v2(91.06,256.92) v2(91.06,212.85) v2(91.06,202.69) v2(91.06,197.61) v2(91.01,132.77) v2(91.06,125.6) v2(91.06,120.52) v2(91.06,116.08) v2(91.06,45.47) v2(91.06,41.78) v2(91.06,40.64) v2(91.06,25.4) v2(91.06,15.24) v2(91.06,10.16) v2(91.06,2.92) v2(91.36,308.93) v2(91.36,219.14) v2(91.36,129.35) v2(91.57,312.31) v2(91.6,222.63) v2(92.3,331.3) v2(92.3,241.51) v2(92.3,151.73) v2(92.3,64.48) v2(92.74,356.23) v2(92.71,79.88) v2(92.96,35.69) v2(93.22,354.33) v2(93.22,349.25) v2(93.22,344.17) v2(93.6,305.18) v2(93.6,289.94) v2(93.6,274.7) v2(93.6,269.62) v2(93.6,264.54) v2(93.6,259.46) v2(93.6,254.38) v2(93.6,215.39) v2(93.6,200.15) v2(93.6,184.91) v2(93.6,164.59) v2(93.6,123.06) v2(93.6,92.58) v2(93.6,38.1) v2(93.6,27.94) v2(93.6,22.86) v2(93.6,12.7) v2(93.6,2.92) v2(94.36,113.54) v2(94.87,184.91) v2(95.28,356.23) v2(95.25,87.5) v2(95.25,82.42) v2(95.25,77.34) v2(95.38,103) v2(95.5,310.57) v2(95.52,220.78) v2(95.53,130.98) v2(95.52,43.73) v2(95.76,351.79) v2(95.76,346.71) v2(96.14,307.72) v2(96.14,302.64) v2(96.14,282.32) v2(96.14,277.24) v2(96.14,272.16) v2(96.14,262) v2(96.14,256.92) v2(96.14,217.93) v2(96.14,212.85) v2(96.14,181.74) v2(96.14,176.15) v2(96.14,167.13) v2(96.14,120.52) v2(96.14,115.44) v2(96.14,95.12) v2(96.14,40.64) v2(96.14,35.56) v2(96.14,15.24) v2(96.14,2.92) v2(96.9,176.78) v2(97.41,39.62) v2(97.79,176.78) v2(97.79,84.96) v2(97.79,79.88) v2(97.82,356.23) v2(98.3,354.33) v2(98.3,349.25) v2(98.3,344.17) v2(98.42,178.56) v2(98.55,177.04) v2(98.68,305.18) v2(98.68,300.1) v2(98.68,274.7) v2(98.68,269.62) v2(98.68,264.54) v2(98.68,259.46) v2(98.68,254.38) v2(98.68,215.39) v2(98.68,210.31) v2(98.68,164.59) v2(98.63,132.77) v2(98.68,112.9) v2(98.68,96.65) v2(98.68,92.58) v2(98.68,45.47) v2(98.68,38.1) v2(98.68,33.02) v2(98.68,2.92) v2(98.93,103.38) v2(99.19,312.31) v2(99.22,222.63) v2(100.2,41.78) v2(100.36,356.23) v2(100.33,87.5) v2(100.33,82.42) v2(100.33,77.34) v2(100.84,351.79) v2(100.84,346.71) v2(101.17,132.77) v2(101.22,307.72) v2(101.22,302.64) v2(101.22,272.16) v2(101.22,262) v2(101.22,256.92) v2(101.22,217.93) v2(101.22,212.85) v2(101.22,182.37) v2(101.22,172.21) v2(101.22,167.13) v2(101.22,45.47) v2(101.22,40.64) v2(101.22,35.56) v2(101.22,2.92) v2(101.35,41.78) v2(102.64,295.15) v2(102.62,292.73) v2(102.64,205.36) v2(102.62,202.95) v2(102.64,115.57) v2(102.62,113.16) v2(102.64,28.32) v2(102.62,25.91) v2(102.9,356.23) v2(102.87,84.96) v2(102.87,79.88) v2(103.12,344.76) v2(103.16,254.99) v2(103.16,165.06) v2(103.17,77.95) v2(103.2,43.74) v2(103.38,354.33) v2(103.38,349.25) v2(103.76,310.55) v2(103.76,305.18) v2(103.76,269.62) v2(103.76,264.54) v2(103.76,259.46) v2(103.76,220.77) v2(103.76,215.39) v2(103.76,179.83) v2(103.76,174.75) v2(103.76,169.67) v2(103.71,132.77) v2(103.76,130.98) v2(103.76,92.58) v2(103.76,45.47) v2(103.76,38.1) v2(103.76,33.02) v2(103.76,2.92) v2(103.84,299.77) v2(103.84,209.98) v2(103.84,120.19) v2(104.27,312.31) v2(104.3,222.63) v2(104.77,41.78) v2(105.44,356.23) v2(105.41,87.5) v2(105.41,82.42) v2(105.65,345.01) v2(105.69,255.19) v2(105.69,165.27) v2(105.7,78.16) v2(105.92,351.79) v2(105.92,346.71) v2(106.3,307.72) v2(106.3,272.16) v2(106.3,262) v2(106.3,256.92) v2(106.3,217.93) v2(106.3,182.37) v2(106.3,172.21) v2(106.3,167.13) v2(106.25,132.77) v2(106.3,130.68) v2(106.3,45.47) v2(106.3,40.64) v2(106.3,2.92) v2(106.81,312.31) v2(106.84,222.63) v2(107.72,282.57) v2(107.72,192.79) v2(107.72,103) v2(107.98,356.23) v2(107.95,84.96) v2(107.95,79.88) v2(108.19,345.01) v2(108.23,255.19) v2(108.23,165.27) v2(108.24,78.16) v2(108.46,354.33) v2(108.46,349.25) v2(108.84,269.62) v2(108.84,264.54) v2(108.84,259.46) v2(108.84,179.83) v2(108.84,174.75) v2(108.84,169.67) v2(108.84,128.14) v2(108.84,92.58) v2(108.84,45.47) v2(108.84,38.1) v2(108.84,2.92) v2(110.49,87.5) v2(110.49,82.42) v2(110.52,356.23) v2(110.73,345.01) v2(110.77,255.19) v2(110.77,165.27) v2(110.78,78.16) v2(111,351.79) v2(111,346.71) v2(111.38,272.16) v2(111.38,262) v2(111.38,256.92) v2(111.38,182.37) v2(111.38,172.21) v2(111.38,167.13) v2(111.33,132.77) v2(111.38,45.47) v2(111.38,5.08) v2(111.38,2.92) v2(111.89,312.31) v2(111.92,222.63) v2(113.06,356.23) v2(113.03,84.96) v2(113.03,79.88) v2(113.27,345.01) v2(113.39,275.26) v2(113.31,255.19) v2(113.39,185.47) v2(113.31,165.27) v2(113.39,95.68) v2(113.32,78.16) v2(113.39,8.43) v2(113.54,354.33) v2(113.54,349.25) v2(113.87,132.77) v2(113.92,310.26) v2(113.92,269.62) v2(113.92,264.54) v2(113.92,259.46) v2(113.92,220.47) v2(113.92,179.83) v2(113.92,174.75) v2(113.92,169.67) v2(113.92,92.58) v2(113.92,45.47) v2(113.92,43.18) v2(113.92,2.92) v2(114.43,312.31) v2(114.46,222.63) v2(114.88,301.34) v2(114.88,211.55) v2(114.88,121.76) v2(114.88,34.52) v2(114.93,275.31) v2(114.93,185.52) v2(114.94,95.73) v2(114.93,8.48) v2(115.6,356.23) v2(115.57,87.5) v2(115.57,82.42) v2(115.81,345.01) v2(115.85,255.19) v2(115.85,165.27) v2(115.86,78.16) v2(116.08,351.79) v2(116.08,346.71) v2(116.46,307.72) v2(116.46,272.16) v2(116.46,262) v2(116.46,256.92) v2(116.46,217.93) v2(116.46,182.37) v2(116.46,172.21) v2(116.46,167.13) v2(116.41,132.77) v2(116.46,130.68) v2(116.46,45.47) v2(116.46,40.64) v2(116.46,5.08) v2(116.46,2.92) v2(116.54,275.3) v2(116.54,185.51) v2(116.54,95.72) v2(116.54,8.47) v2(116.97,312.31) v2(117,222.63) v2(117.21,301.33) v2(117.21,211.55) v2(117.21,121.76) v2(117.21,34.51) v2(117.4,294.78) v2(117.4,204.99) v2(117.4,115.2) v2(117.4,27.95) v2(118.01,275.26) v2(118.01,185.47) v2(118.01,95.68) v2(118.01,8.43) v2(118.14,356.23) v2(118.11,84.96) v2(118.11,79.88) v2(118.35,345.01) v2(118.39,255.19) v2(118.39,165.27) v2(118.4,78.16) v2(119,310.26) v2(118.99,286.01) v2(119,269.62) v2(119,220.47) v2(118.99,196.22) v2(119,179.83) v2(118.95,132.77) v2(119,128.14) v2(118.99,106.43) v2(119,92.58) v2(119,45.47) v2(119,43.18) v2(118.99,19.18) v2(119,2.92) v2(119.43,38.18) v2(119.58,278.13) v2(119.58,188.34) v2(119.58,98.55) v2(119.58,11.3) v2(120.13,286.01) v2(120.13,196.22) v2(120.13,106.43) v2(120.13,19.18) v2(120.68,356.23) v2(120.89,345.01) v2(120.83,293.93) v2(120.83,204.14) v2(120.83,114.35) v2(120.83,27.1) v2(120.93,255.19) v2(120.93,165.27) v2(120.94,78.16) v2(121.16,346.71) v2(121.54,272.16) v2(121.54,256.92) v2(121.54,182.37) v2(121.54,167.13) v2(121.54,5.08) v2(121.54,2.92) v2(122.08,222.63) v2(123.19,79.88) v2(123.22,356.23) v2(123.43,345.01) v2(123.47,255.19) v2(123.47,165.27) v2(123.48,78.16) v2(124.08,269.62) v2(124.08,179.83) v2(124.08,92.58) v2(124.08,2.92) v2(124.18,278.56) v2(124.18,188.77) v2(124.18,98.98) v2(124.18,11.74) v2(124.71,97.79) v2(125.76,356.23) v2(125.97,345.01) v2(126.01,255.19) v2(126.01,165.27) v2(126.02,78.16) v2(126.24,346.71) v2(126.62,272.16) v2(126.62,262) v2(126.62,256.92) v2(126.62,182.37) v2(126.62,172.21) v2(126.62,167.13) v2(126.62,5.08) v2(126.62,2.92) v2(127.38,184.91) v2(127.63,274.19) v2(128.3,356.23) v2(128.27,84.96) v2(128.27,79.88) v2(128.51,345.01) v2(128.55,255.19) v2(128.55,165.27) v2(128.56,78.16) v2(128.78,354.33) v2(128.78,349.25) v2(128.83,293.93) v2(128.83,292.79) v2(128.83,287.45) v2(128.83,204.14) v2(128.83,203) v2(128.83,197.66) v2(128.83,114.35) v2(128.83,113.21) v2(128.83,107.87) v2(128.83,27.1) v2(128.83,25.96) v2(128.83,20.12) v2(129.16,310.26) v2(129.16,305.18) v2(129.16,300.1) v2(129.16,269.62) v2(129.16,264.54) v2(129.16,259.46) v2(129.16,220.47) v2(129.16,179.83) v2(129.16,174.75) v2(129.16,169.67) v2(129.16,128.14) v2(129.16,123.06) v2(129.16,117.98) v2(129.16,92.58) v2(129.16,45.47) v2(129.16,43.18) v2(129.16,38.1) v2(129.16,33.02) v2(129.16,2.92) v2(129.67,312.31) v2(129.7,222.63) v2(130.84,356.23) v2(130.81,87.5) v2(130.81,82.42) v2(131.05,345.01) v2(131.09,255.19) v2(131.09,165.27) v2(131.1,78.16) v2(131.32,351.79) v2(131.32,346.71) v2(131.7,307.72) v2(131.7,302.64) v2(131.7,297.56) v2(131.7,292.48) v2(131.7,287.4) v2(131.7,282.32) v2(131.7,277.24) v2(131.7,272.16) v2(131.7,262) v2(131.7,256.92) v2(131.7,217.93) v2(131.7,212.85) v2(131.7,207.77) v2(131.7,202.69) v2(131.7,197.61) v2(131.7,192.53) v2(131.7,182.37) v2(131.7,172.21) v2(131.7,167.13) v2(131.65,132.77) v2(131.7,130.68) v2(131.7,125.6) v2(131.7,120.52) v2(131.7,115.44) v2(131.7,105.28) v2(131.7,100.97) v2(131.7,45.47) v2(131.7,40.64) v2(131.7,35.56) v2(131.7,30.48) v2(131.7,25.4) v2(131.7,20.32) v2(131.7,15.24) v2(131.7,5.08) v2(131.7,2.92) v2(131.95,10.67) v2(132.21,312.31) v2(132.24,222.63) v2(133.1,188.09) v2(133.38,356.23) v2(133.35,84.96) v2(133.35,79.88) v2(133.59,345.01) v2(133.63,255.19) v2(133.63,165.27) v2(133.64,78.16) v2(133.86,354.33) v2(133.86,349.25) v2(134.19,132.77) v2(134.24,310.26) v2(134.24,305.18) v2(134.24,300.1) v2(134.24,295.02) v2(134.24,284.86) v2(134.24,279.78) v2(134.24,269.62) v2(134.24,264.54) v2(134.24,259.46) v2(134.24,220.47) v2(134.24,215.39) v2(134.24,210.31) v2(134.24,205.23) v2(134.24,195.07) v2(134.24,189.48) v2(134.24,179.83) v2(134.24,174.75) v2(134.24,169.67) v2(134.24,128.14) v2(134.24,123.06) v2(134.24,117.98) v2(134.24,112.9) v2(134.24,107.82) v2(134.24,102.74) v2(134.24,97.66) v2(134.24,92.58) v2(134.24,45.47) v2(134.24,43.18) v2(134.24,38.1) v2(134.24,33.02) v2(134.24,27.94) v2(134.24,17.78) v2(134.24,7.62) v2(134.24,2.92) v2(134.49,10.79) v2(134.75,312.31) v2(134.78,222.63) v2(135.89,87.5) v2(135.89,82.42) v2(135.92,356.23) v2(136.13,345.01) v2(136.17,255.19) v2(136.17,165.27) v2(136.18,78.16) v2(136.4,351.79) v2(136.4,346.71) v2(136.65,10.67) v2(136.78,302.64) v2(136.78,297.56) v2(136.78,292.48) v2(136.78,287.4) v2(136.78,282.32) v2(136.78,277.24) v2(136.78,272.16) v2(136.78,262) v2(136.78,256.92) v2(136.78,212.85) v2(136.78,207.77) v2(136.78,202.69) v2(136.78,197.61) v2(136.78,192.53) v2(136.78,187.45) v2(136.78,182.37) v2(136.78,172.21) v2(136.78,167.13) v2(136.73,132.77) v2(136.78,130.68) v2(136.78,125.6) v2(136.78,120.52) v2(136.78,115.44) v2(136.78,105.28) v2(136.78,100.97) v2(136.78,45.47) v2(136.78,35.56) v2(136.78,30.48) v2(136.78,25.4) v2(136.78,20.32) v2(136.78,15.24) v2(136.78,5.08) v2(136.78,2.92) v2(137.29,312.31) v2(137.29,308.61) v2(137.29,307.47) v2(137.29,218.82) v2(137.29,217.68) v2(137.29,129.03) v2(137.29,127.89) v2(137.29,41.78) v2(137.29,40.64) v2(137.32,222.63) v2(138.18,343.3) v2(138.18,163.67) v2(138.18,76.42) v2(138.34,253.37) v2(138.46,356.23) v2(138.43,308.61) v2(138.43,307.47) v2(138.43,218.82) v2(138.43,217.68) v2(138.43,129.03) v2(138.43,127.89) v2(138.43,84.96) v2(138.43,79.88) v2(138.43,41.78) v2(138.43,40.64) v2(138.81,10.79) v2(138.94,354.33) v2(138.94,349.25) v2(138.94,344.17) v2(139.27,132.77) v2(139.32,305.18) v2(139.32,300.1) v2(139.32,295.02) v2(139.32,284.86) v2(139.32,279.78) v2(139.32,269.62) v2(139.32,264.54) v2(139.32,259.46) v2(139.32,254.38) v2(139.32,215.39) v2(139.32,210.31) v2(139.32,205.23) v2(139.32,195.07) v2(139.32,189.48) v2(139.32,179.83) v2(139.32,174.75) v2(139.32,169.67) v2(139.32,164.59) v2(139.32,123.06) v2(139.32,117.98) v2(139.32,112.9) v2(139.32,107.82) v2(139.32,102.74) v2(139.32,97.66) v2(139.32,92.58) v2(139.32,45.47) v2(139.32,38.1) v2(139.32,33.02) v2(139.32,27.94) v2(139.32,17.78) v2(139.32,7.62) v2(139.32,2.92) v2(139.57,308.61) v2(139.57,307.47) v2(139.57,218.82) v2(139.57,217.68) v2(139.57,129.03) v2(139.57,127.89) v2(139.57,41.78) v2(139.57,40.64) v2(139.83,312.34) v2(139.86,222.63) v2(140.69,331.36) v2(140.66,64.47) v2(140.72,310.43) v2(140.72,308.61) v2(140.72,307.47) v2(140.78,241.55) v2(140.72,220.64) v2(140.72,218.82) v2(140.72,217.68) v2(140.72,151.73) v2(140.72,130.85) v2(140.72,129.03) v2(140.72,127.89) v2(140.72,43.6) v2(140.72,41.78) v2(140.72,40.64) v2(141,356.23) v2(140.97,87.5) v2(140.97,82.42) v2(140.97,77.34) v2(141.48,351.79) v2(141.48,346.71) v2(141.86,308.61) v2(141.86,307.47) v2(141.86,302.64) v2(141.86,297.56) v2(141.86,292.48) v2(141.86,287.4) v2(141.86,282.32) v2(141.86,277.24) v2(141.86,272.16) v2(141.86,262) v2(141.86,256.92) v2(141.86,218.82) v2(141.86,217.68) v2(141.86,212.85) v2(141.86,207.77) v2(141.86,202.69) v2(141.86,197.61) v2(141.86,192.53) v2(141.86,187.45) v2(141.86,182.37) v2(141.86,172.21) v2(141.86,167.13) v2(141.81,132.77) v2(141.86,129.03) v2(141.86,127.89) v2(141.86,125.6) v2(141.86,120.52) v2(141.86,115.44) v2(141.86,105.28) v2(141.86,100.97) v2(141.86,45.47) v2(141.86,41.78) v2(141.86,40.64) v2(141.86,35.56) v2(141.86,30.48) v2(141.86,25.4) v2(141.86,20.32) v2(141.86,15.24) v2(141.86,5.08) v2(141.86,2.92) v2(142.37,312.34) v2(142.4,222.63) v2(143,308.61) v2(143,307.47) v2(143,218.82) v2(143,217.68) v2(143,129.03) v2(143,127.89) v2(143,41.78) v2(143,40.64) v2(143.54,356.23) v2(143.51,84.96) v2(143.51,79.88) v2(144.02,354.33) v2(144.02,349.25) v2(144.14,308.61) v2(144.14,307.47) v2(144.14,218.82) v2(144.14,217.68) v2(144.14,129.03) v2(144.14,127.89) v2(144.14,41.78) v2(144.14,40.64) v2(144.26,7.65) v2(144.4,305.18) v2(144.4,300.1) v2(144.4,295.02) v2(144.4,284.86) v2(144.4,279.78) v2(144.4,269.62) v2(144.4,264.54) v2(144.4,259.46) v2(144.4,215.39) v2(144.4,210.31) v2(144.4,205.23) v2(144.4,195.07) v2(144.4,189.48) v2(144.4,179.83) v2(144.4,174.75) v2(144.4,169.67) v2(144.35,132.77) v2(144.4,123.06) v2(144.4,117.98) v2(144.4,112.9) v2(144.4,107.82) v2(144.4,102.74) v2(144.4,97.66) v2(144.4,92.58) v2(144.4,45.47) v2(144.4,38.1) v2(144.4,33.02) v2(144.4,27.94) v2(144.4,17.78) v2(144.4,15.37) v2(144.4,2.92) v2(144.89,343.33) v2(144.88,253.48) v2(144.91,345.44) v2(144.91,344.3) v2(144.91,312.34) v2(144.91,255.65) v2(144.91,254.51) v2(144.94,222.63) v2(144.91,165.86) v2(144.91,164.72) v2(144.91,78.61) v2(144.91,77.47) v2(144.92,76.38) v2(145.29,308.61) v2(145.29,307.47) v2(145.29,218.82) v2(145.29,217.68) v2(145.29,129.03) v2(145.29,127.89) v2(145.29,41.78) v2(145.29,40.64) v2(146.08,356.23) v2(146.05,345.44) v2(146.05,344.3) v2(146.05,343.15) v2(146.05,255.65) v2(146.05,254.51) v2(146.05,253.36) v2(146.05,165.86) v2(146.05,164.72) v2(146.05,163.58) v2(146.05,87.5) v2(146.05,82.42) v2(146.05,78.61) v2(146.05,77.47) v2(146.05,76.33) v2(146.43,308.61) v2(146.43,307.47) v2(146.43,218.82) v2(146.43,217.68) v2(146.43,129.03) v2(146.43,127.89) v2(146.43,41.78) v2(146.43,40.64) v2(146.56,351.79) v2(146.89,132.77) v2(146.94,302.64) v2(146.94,297.56) v2(146.94,292.48) v2(146.94,287.4) v2(146.94,282.32) v2(146.94,277.24) v2(146.94,272.16) v2(146.94,262) v2(146.94,212.85) v2(146.94,207.77) v2(146.94,202.69) v2(146.94,197.61) v2(146.94,192.53) v2(146.94,187.45) v2(146.94,182.37) v2(146.94,172.21) v2(146.94,125.6) v2(146.94,120.52) v2(146.94,115.44) v2(146.94,105.28) v2(146.94,100.97) v2(146.94,45.47) v2(146.94,35.56) v2(146.94,30.48) v2(146.94,25.4) v2(146.94,20.32) v2(146.94,15.24) v2(146.94,9.4) v2(146.94,5.08) v2(146.94,2.92) v2(147.07,310.43) v2(147.07,220.64) v2(147.07,130.85) v2(147.07,43.6) v2(147.19,345.44) v2(147.19,344.3) v2(147.19,343.15) v2(147.19,255.65) v2(147.19,254.51) v2(147.19,253.36) v2(147.19,165.86) v2(147.19,164.72) v2(147.19,163.58) v2(147.19,78.61) v2(147.19,77.47) v2(147.19,76.33) v2(147.45,312.34) v2(147.48,222.63) v2(147.57,308.61) v2(147.57,307.47) v2(147.57,218.82) v2(147.57,217.68) v2(147.57,129.03) v2(147.57,127.89) v2(147.57,41.78) v2(147.57,40.64) v2(148.34,345.44) v2(148.34,344.3) v2(148.34,343.15) v2(148.34,255.65) v2(148.34,254.51) v2(148.34,253.36) v2(148.34,165.86) v2(148.34,164.72) v2(148.34,163.58) v2(148.34,78.61) v2(148.34,77.47) v2(148.34,76.33) v2(148.59,84.96) v2(148.59,79.88) v2(148.62,356.23) v2(148.72,308.61) v2(148.72,307.47) v2(148.72,218.82) v2(148.72,217.68) v2(148.72,129.03) v2(148.72,127.89) v2(148.72,41.78) v2(148.72,40.64) v2(149.1,354.33) v2(149.1,349.25) v2(149.48,345.44) v2(149.48,344.3) v2(149.48,343.15) v2(149.48,305.18) v2(149.48,300.1) v2(149.48,295.02) v2(149.48,284.86) v2(149.48,279.78) v2(149.48,274.7) v2(149.48,269.62) v2(149.48,264.54) v2(149.48,259.46) v2(149.48,255.65) v2(149.48,254.51) v2(149.48,253.36) v2(149.48,215.39) v2(149.48,210.31) v2(149.48,205.23) v2(149.48,195.07) v2(149.48,189.48) v2(149.48,184.91) v2(149.48,179.83) v2(149.48,174.75) v2(149.48,169.67) v2(149.48,165.86) v2(149.48,164.72) v2(149.48,163.58) v2(149.43,132.77) v2(149.48,123.06) v2(149.48,117.98) v2(149.48,112.9) v2(149.48,107.82) v2(149.48,102.74) v2(149.48,97.66) v2(149.48,92.58) v2(149.48,78.61) v2(149.48,77.47) v2(149.48,76.33) v2(149.48,45.47) v2(149.48,38.1) v2(149.48,33.02) v2(149.48,27.94) v2(149.48,17.78) v2(149.48,7.62) v2(149.48,2.92) v2(149.86,308.61) v2(149.86,307.47) v2(149.86,218.82) v2(149.86,217.68) v2(149.86,129.03) v2(149.86,127.89) v2(149.86,41.78) v2(149.86,40.64) v2(149.99,312.34) v2(150.02,222.63) v2(150.62,345.44) v2(150.62,344.3) v2(150.62,343.15) v2(150.62,255.65) v2(150.62,254.51) v2(150.62,253.36) v2(150.62,165.86) v2(150.62,164.72) v2(150.62,163.58) v2(150.62,78.61) v2(150.62,77.47) v2(150.62,76.33) v2(151,308.61) v2(151,307.47) v2(151,218.82) v2(151,217.68) v2(151,129.03) v2(151,127.89) v2(151,41.78) v2(151,40.64) v2(151.16,356.23) v2(151.13,87.5) v2(151.13,82.42) v2(151.26,13.97) v2(151.64,351.79) v2(151.76,345.44) v2(151.76,344.3) v2(151.76,343.15) v2(151.76,255.65) v2(151.76,254.51) v2(151.76,253.36) v2(151.77,165.86) v2(151.77,164.72) v2(151.77,163.58) v2(151.76,78.61) v2(151.76,77.47) v2(151.76,76.33) v2(151.89,9.53) v2(151.97,132.77) v2(152.02,302.64) v2(152.02,297.56) v2(152.02,292.48) v2(152.02,287.4) v2(152.02,282.32) v2(152.02,277.24) v2(152.02,272.16) v2(152.02,262) v2(152.02,212.85) v2(152.02,207.77) v2(152.02,202.69) v2(152.02,197.61) v2(152.02,192.53) v2(152.02,187.45) v2(152.02,182.37) v2(152.02,172.21) v2(152.02,167.13) v2(152.02,125.6) v2(152.02,120.52) v2(152.02,115.44) v2(152.02,105.28) v2(152.02,100.97) v2(152.02,95.12) v2(152.02,45.47) v2(152.02,35.56) v2(152.02,30.48) v2(152.02,20.32) v2(152.02,15.24) v2(152.02,5.08) v2(152.02,2.92) v2(152.15,308.61) v2(152.15,307.47) v2(152.15,218.82) v2(152.15,217.68) v2(152.15,129.03) v2(152.15,127.89) v2(152.15,41.78) v2(152.15,40.64) v2(152.27,25.38) v2(152.53,312.34) v2(152.56,222.63) v2(152.91,345.44) v2(152.91,344.3) v2(152.91,343.15) v2(152.91,255.65) v2(152.91,254.51) v2(152.91,253.36) v2(152.91,165.86) v2(152.91,164.72) v2(152.91,163.58) v2(152.91,78.61) v2(152.91,77.47) v2(152.91,76.33) v2(153.29,308.61) v2(153.29,307.47) v2(153.29,218.82) v2(153.29,217.68) v2(153.29,129.03) v2(153.29,127.89) v2(153.29,41.78) v2(153.29,40.64) v2(153.42,310.43) v2(153.42,220.64) v2(153.42,130.85) v2(153.42,43.6) v2(153.54,331.18) v2(153.7,356.23) v2(153.7,241.39) v2(153.7,151.6) v2(153.67,84.96) v2(153.67,79.88) v2(153.7,64.6) v2(154.05,345.44) v2(154.05,344.3) v2(154.05,343.15) v2(154.05,255.65) v2(154.05,254.51) v2(154.05,253.36) v2(154.05,165.86) v2(154.05,164.72) v2(154.05,163.58) v2(154.05,78.61) v2(154.05,77.47) v2(154.05,76.33) v2(154.18,354.33) v2(154.18,349.25) v2(154.43,308.61) v2(154.43,307.47) v2(154.43,218.82) v2(154.43,217.68) v2(154.43,129.03) v2(154.43,127.89) v2(154.43,41.78) v2(154.43,40.64) v2(154.56,305.18) v2(154.56,300.1) v2(154.56,295.02) v2(154.56,284.86) v2(154.56,279.78) v2(154.56,274.7) v2(154.56,269.62) v2(154.56,264.54) v2(154.56,259.46) v2(154.56,215.39) v2(154.56,210.31) v2(154.56,205.23) v2(154.56,195.07) v2(154.56,189.99) v2(154.56,184.91) v2(154.56,179.83) v2(154.56,174.75) v2(154.56,169.67) v2(154.51,132.77) v2(154.56,123.06) v2(154.56,117.98) v2(154.56,112.9) v2(154.56,107.82) v2(154.56,102.74) v2(154.56,97.66) v2(154.56,92.58) v2(154.56,45.47) v2(154.56,38.1) v2(154.56,33.02) v2(154.56,17.78) v2(154.56,7.62) v2(154.56,2.92) v2(154.81,27.92) v2(154.94,14.1) v2(155.07,312.34) v2(155.19,345.44) v2(155.19,344.3) v2(155.19,343.15) v2(155.19,255.65) v2(155.19,254.51) v2(155.19,253.36) v2(155.1,222.63) v2(155.19,165.86) v2(155.19,164.72) v2(155.19,163.58) v2(155.19,78.61) v2(155.19,77.47) v2(155.19,76.33) v2(155.57,308.61) v2(155.57,307.47) v2(155.57,218.82) v2(155.57,217.68) v2(155.57,129.03) v2(155.57,127.89) v2(155.57,41.78) v2(155.57,40.64) v2(156.24,356.23) v2(156.21,87.5) v2(156.21,82.42) v2(156.34,345.44) v2(156.34,344.3) v2(156.35,343.26) v2(156.34,255.65) v2(156.34,254.51) v2(156.33,253.37) v2(156.34,165.86) v2(156.34,164.72) v2(156.34,163.58) v2(156.34,78.61) v2(156.34,77.47) v2(156.32,76.39) v2(156.72,351.79) v2(156.72,308.61) v2(156.72,307.47) v2(156.72,218.82) v2(156.72,217.68) v2(156.72,129.03) v2(156.72,127.89) v2(156.72,41.78) v2(156.72,40.64) v2(157.1,302.64) v2(157.1,297.56) v2(157.1,292.48) v2(157.1,287.4) v2(157.1,282.32) v2(157.1,277.24) v2(157.1,272.16) v2(157.1,262) v2(157.1,212.85) v2(157.1,207.77) v2(157.1,202.69) v2(157.1,197.61) v2(157.1,192.53) v2(157.1,187.45) v2(157.1,182.37) v2(157.1,172.21) v2(157.1,167.13) v2(157.05,132.77) v2(157.1,130.68) v2(157.1,125.6) v2(157.1,120.52) v2(157.1,115.44) v2(157.1,105.28) v2(157.1,100.97) v2(157.1,95.12) v2(157.1,45.47) v2(157.1,35.56) v2(157.1,25.4) v2(157.1,20.32) v2(157.1,5.08) v2(157.1,2.92) v2(157.23,9.4) v2(157.35,30.46) v2(157.35,16.26) v2(157.48,345.44) v2(157.48,344.3) v2(157.49,343.26) v2(157.48,255.65) v2(157.48,254.51) v2(157.47,253.47) v2(157.48,165.86) v2(157.48,164.72) v2(157.48,163.64) v2(157.48,78.61) v2(157.48,77.47) v2(157.44,76.39) v2(157.61,312.34) v2(157.64,222.63) v2(158.58,76.39) v2(158.62,345.44) v2(158.62,344.3) v2(158.62,343.24) v2(158.62,255.65) v2(158.62,254.51) v2(158.64,253.47) v2(158.62,165.86) v2(158.62,164.72) v2(158.62,163.64) v2(158.62,78.61) v2(158.62,77.47) v2(158.78,356.23) v2(158.75,84.96) v2(158.75,79.88) v2(159.26,354.33) v2(159.26,349.25) v2(159.59,132.77) v2(159.51,15.24) v2(159.64,310.26) v2(159.64,305.18) v2(159.64,300.1) v2(159.64,295.02) v2(159.64,284.86) v2(159.64,279.78) v2(159.64,274.7) v2(159.64,269.62) v2(159.64,264.54) v2(159.64,259.46) v2(159.64,220.47) v2(159.64,215.39) v2(159.64,210.31) v2(159.64,205.23) v2(159.64,195.07) v2(159.64,189.99) v2(159.64,184.91) v2(159.64,179.83) v2(159.64,174.75) v2(159.64,169.67) v2(159.64,123.06) v2(159.64,117.98) v2(159.64,112.9) v2(159.64,107.82) v2(159.64,102.74) v2(159.64,97.66) v2(159.64,92.58) v2(159.64,45.47) v2(159.64,43.18) v2(159.64,38.1) v2(159.64,27.94) v2(159.64,17.78) v2(159.64,7.62) v2(159.64,2.92) v2(159.77,345.44) v2(159.77,344.3) v2(159.77,343.15) v2(159.77,255.65) v2(159.77,254.51) v2(159.77,253.36) v2(159.77,165.86) v2(159.77,164.72) v2(159.77,163.58) v2(159.77,78.61) v2(159.77,77.47) v2(159.77,76.33) v2(159.89,33) v2(160.15,312.34) v2(160.18,222.63) v2(160.91,345.44) v2(160.91,344.3) v2(160.91,343.15) v2(160.91,255.65) v2(160.91,254.51) v2(160.91,253.36) v2(160.91,165.86) v2(160.91,164.72) v2(160.91,163.58) v2(160.91,78.61) v2(160.91,77.47) v2(160.91,76.33) v2(161.29,87.5) v2(161.29,82.42) v2(161.32,356.23) v2(161.8,351.79) v2(161.92,218.82) v2(161.93,129.03) v2(161.92,41.78) v2(162.05,345.44) v2(162.05,344.3) v2(162.05,343.15) v2(162.05,255.65) v2(162.05,254.51) v2(162.05,253.36) v2(162.05,165.86) v2(162.05,164.72) v2(162.05,163.58) v2(162.05,78.61) v2(162.05,77.47) v2(162.05,76.33) v2(162.18,302.64) v2(162.18,297.56) v2(162.18,282.32) v2(162.18,277.24) v2(162.18,272.16) v2(162.18,262) v2(162.18,212.85) v2(162.18,207.77) v2(162.18,192.53) v2(162.18,187.45) v2(162.18,182.37) v2(162.18,172.21) v2(162.13,132.77) v2(162.18,125.6) v2(162.18,120.52) v2(162.18,115.44) v2(162.18,105.28) v2(162.18,100.97) v2(162.18,95.12) v2(162.18,45.47) v2(162.18,30.48) v2(162.18,25.4) v2(162.18,10.16) v2(162.18,5.08) v2(162.18,2.92) v2(162.43,35.54) v2(162.43,16.26) v2(162.69,312.34) v2(162.72,222.63) v2(163.86,356.23) v2(163.88,308.63) v2(163.88,218.82) v2(163.88,129.03) v2(163.83,84.96) v2(163.83,79.88) v2(163.83,69.72) v2(163.89,41.78) v2(164.34,354.33) v2(164.34,349.25) v2(164.34,344.17) v2(164.34,339.09) v2(164.67,132.77) v2(164.72,300.1) v2(164.72,284.86) v2(164.72,279.78) v2(164.72,274.7) v2(164.72,269.62) v2(164.72,264.54) v2(164.72,259.46) v2(164.72,254.38) v2(164.72,249.3) v2(164.72,210.31) v2(164.72,195.07) v2(164.72,189.99) v2(164.72,184.91) v2(164.72,179.83) v2(164.72,174.75) v2(164.72,169.67) v2(164.72,164.59) v2(164.72,159.51) v2(164.72,154.43) v2(164.72,123.06) v2(164.72,117.98) v2(164.72,112.9) v2(164.72,107.82) v2(164.72,102.74) v2(164.72,97.66) v2(164.72,92.58) v2(164.72,45.47) v2(164.72,33.02) v2(164.72,27.94) v2(164.72,17.78) v2(164.72,11.94) v2(164.72,7.62) v2(164.72,2.92) v2(164.85,244.22) v2(164.97,38.06) v2(165.23,312.34) v2(165.26,222.63) v2(165.62,329.31) v2(165.62,62.55) v2(165.76,149.73) v2(166.18,239.69) v2(166.24,243.01) v2(166.4,356.23) v2(166.37,87.5) v2(166.37,82.42) v2(166.37,77.34) v2(166.37,72.26) v2(166.69,331.18) v2(166.71,241.39) v2(166.71,151.6) v2(166.71,64.35) v2(166.88,351.79) v2(166.88,346.71) v2(166.88,341.63) v2(166.88,336.55) v2(167.26,307.72) v2(167.26,302.64) v2(167.26,287.4) v2(167.26,282.32) v2(167.26,277.24) v2(167.26,272.16) v2(167.26,262) v2(167.26,256.92) v2(167.26,251.84) v2(167.26,246.76) v2(167.26,217.93) v2(167.26,212.85) v2(167.26,197.61) v2(167.26,192.53) v2(167.26,187.45) v2(167.26,182.37) v2(167.26,172.21) v2(167.26,167.13) v2(167.26,162.05) v2(167.26,156.97) v2(167.21,132.77) v2(167.26,130.68) v2(167.26,125.6) v2(167.26,120.52) v2(167.26,115.44) v2(167.26,110.36) v2(167.26,105.28) v2(167.26,100.97) v2(167.26,95.12) v2(167.26,45.47) v2(167.26,35.56) v2(167.26,30.48) v2(167.26,20.32) v2(167.26,10.16) v2(167.26,5.08) v2(167.26,2.92) v2(167.51,40.62) v2(167.77,312.22) v2(167.77,222.43) v2(168.16,329.31) v2(168.17,149.73) v2(168.16,62.55) v2(168.59,239.69) v2(168.81,38.06) v2(168.94,356.23) v2(168.91,84.96) v2(168.91,79.88) v2(168.91,74.8) v2(168.91,69.72) v2(169.42,354.33) v2(169.42,349.25) v2(169.42,344.17) v2(169.42,339.09) v2(169.42,14.1) v2(169.8,300.1) v2(169.8,289.94) v2(169.8,284.86) v2(169.8,279.78) v2(169.8,274.7) v2(169.8,269.62) v2(169.8,264.54) v2(169.8,259.46) v2(169.8,254.38) v2(169.8,249.3) v2(169.8,210.31) v2(169.8,200.15) v2(169.8,195.07) v2(169.8,189.99) v2(169.8,184.91) v2(169.8,179.83) v2(169.8,174.75) v2(169.8,169.67) v2(169.8,164.59) v2(169.8,159.51) v2(169.8,123.06) v2(169.8,117.98) v2(169.8,112.9) v2(169.8,107.82) v2(169.8,102.74) v2(169.8,97.66) v2(169.8,92.58) v2(169.8,33.02) v2(169.8,22.86) v2(169.8,11.94) v2(169.8,7.62) v2(169.8,2.92) v2(170.56,338.11) v2(170.7,62.55) v2(170.7,329.31) v2(170.71,149.73) v2(171.13,239.69) v2(171.48,356.23) v2(171.45,87.5) v2(171.45,82.42) v2(171.45,77.34) v2(171.45,72.26) v2(171.7,16.76) v2(171.96,351.79) v2(171.96,346.71) v2(171.96,341.63) v2(171.96,331.47) v2(171.96,182.12) v2(172.34,292.48) v2(172.34,287.4) v2(172.34,282.32) v2(172.34,277.24) v2(172.34,272.16) v2(172.34,262) v2(172.34,256.92) v2(172.34,251.84) v2(172.35,244.42) v2(172.34,241.68) v2(172.34,202.69) v2(172.34,197.61) v2(172.34,192.53) v2(172.34,187.45) v2(172.34,172.21) v2(172.34,167.13) v2(172.34,162.05) v2(172.35,154.63) v2(172.34,151.89) v2(172.34,115.44) v2(172.34,110.36) v2(172.34,105.28) v2(172.34,100.97) v2(172.34,95.12) v2(172.35,67.56) v2(172.34,25.4) v2(172.34,10.16) v2(172.34,5.08) v2(172.34,2.92) v2(172.59,334.16) v2(172.59,14.1) v2(172.97,279.78) v2(173.1,18.92) v2(173.24,329.31) v2(173.25,149.73) v2(173.24,62.55) v2(173.67,239.69) v2(173.99,113.17) v2(173.99,110.63) v2(173.99,108.09) v2(173.99,105.55) v2(173.99,103.01) v2(173.99,101.24) v2(173.99,95.39) v2(173.99,92.85) v2(173.99,87.5) v2(173.99,84.96) v2(173.99,82.42) v2(173.99,79.88) v2(173.99,77.61) v2(173.99,74.8) v2(173.99,72.26) v2(173.99,69.72) v2(173.99,64.64) v2(174.13,204.47) v2(174.37,354.45) v2(174.37,351.91) v2(174.37,349.37) v2(174.37,346.83) v2(174.37,344.29) v2(174.37,341.75) v2(174.37,339.21) v2(174.37,336.67) v2(174.37,331.59) v2(174.37,297.68) v2(174.37,295.14) v2(174.37,292.6) v2(174.37,290.06) v2(174.37,287.52) v2(174.37,284.98) v2(174.37,282.44) v2(174.37,274.82) v2(174.37,272.28) v2(174.37,269.74) v2(174.37,264.66) v2(174.37,262.12) v2(174.37,259.58) v2(174.37,257.04) v2(174.37,254.5) v2(174.37,251.96) v2(174.37,249.42) v2(174.37,246.88) v2(174.37,241.8) v2(174.39,202.81) v2(174.39,200.27) v2(174.39,197.73) v2(174.39,195.19) v2(174.39,192.65) v2(174.39,190.11) v2(174.39,185.03) v2(174.39,174.87) v2(174.39,172.33) v2(174.39,169.79) v2(174.39,167.25) v2(174.39,164.71) v2(174.39,162.17) v2(174.39,159.63) v2(174.39,157.09) v2(174.39,152.01) v2(174.71,28.19) v2(174.71,20.57) v2(174.71,12.19) v2(174.71,10.41) v2(174.71,7.87) v2(174.71,5.08) v2(174.71,2.92) v2(174.97,16.5) v2(175.01,178.94) v2(175.13,182.75) v2(175.13,21.59) v2(175.26,14.61) v2(185.75,196.72) v2(185.75,173.86) v2(186.18,199.17) v2(186.18,194.27) v2(186.18,176.31) v2(186.18,171.41) v2(187.43,201.33) v2(187.43,192.12) v2(187.43,178.47) v2(187.43,169.26) v2(189.33,202.93) v2(189.33,190.52) v2(189.33,180.07) v2(189.33,167.66) v2(191.26,160.15) v2(191.24,157.1) v2(191.67,203.78) v2(191.67,189.67) v2(191.67,180.92) v2(191.67,166.81) v2(192.28,157.1) v2(192.3,160.15) v2(193.29,157.1) v2(193.32,160.15) v2(194.16,203.78) v2(194.16,189.67) v2(194.16,180.92) v2(194.16,166.81) v2(194.39,157.1) v2(194.41,160.15) v2(196.49,202.93) v2(196.49,190.52) v2(196.49,180.07) v2(196.49,167.66) v2(198.4,201.33) v2(198.4,192.12) v2(198.4,178.47) v2(198.4,169.26) v2(199.64,199.17) v2(199.64,194.27) v2(199.64,176.31) v2(199.64,171.41) v2(200.08,196.72) v2(200.08,173.86) v3(112.41,292.09) v3(112.41,291.2) v3(112.41,290.31) v3(112.41,289.42) v3(112.41,288.53) v3(112.41,202.3) v3(112.41,201.41) v3(112.41,200.52) v3(112.41,199.63) v3(112.41,198.74) v3(112.41,112.51) v3(112.41,111.62) v3(112.41,110.73) v3(112.41,109.84) v3(112.41,108.95) v3(112.41,25.26) v3(112.41,24.37) v3(112.41,23.48) v3(112.41,22.59) v3(112.41,21.7) v3(113.3,292.09) v3(113.3,291.2) v3(113.3,290.31) v3(113.3,289.42) v3(113.3,288.53) v3(113.3,202.3) v3(113.3,201.41) v3(113.3,200.52) v3(113.3,199.63) v3(113.3,198.74) v3(113.3,112.51) v3(113.3,111.62) v3(113.3,110.73) v3(113.3,109.84) v3(113.3,108.95) v3(113.3,25.26) v3(113.3,24.37) v3(113.3,23.48) v3(113.3,22.59) v3(113.3,21.7) v3(114.18,292.09) v3(114.18,291.2) v3(114.18,290.31) v3(114.18,289.42) v3(114.18,288.53) v3(114.18,202.3) v3(114.18,201.41) v3(114.18,200.52) v3(114.18,199.63) v3(114.18,198.74) v3(114.19,112.51) v3(114.19,111.62) v3(114.19,110.73) v3(114.19,109.84) v3(114.19,108.95) v3(114.18,25.26) v3(114.18,24.37) v3(114.18,23.48) v3(114.18,22.59) v3(114.18,21.7) v3(115.07,292.09) v3(115.07,291.2) v3(115.07,290.31) v3(115.07,289.42) v3(115.07,288.53) v3(115.07,202.3) v3(115.07,201.41) v3(115.07,200.52) v3(115.07,199.63) v3(115.07,198.74) v3(115.07,112.51) v3(115.07,111.62) v3(115.07,110.73) v3(115.07,109.84) v3(115.07,108.95) v3(115.07,25.26) v3(115.07,24.37) v3(115.07,23.48) v3(115.07,22.59) v3(115.07,21.7) v3(115.96,292.09) v3(115.96,291.2) v3(115.96,290.31) v3(115.96,289.42) v3(115.96,288.53) v3(115.96,202.3) v3(115.96,201.41) v3(115.96,200.52) v3(115.96,199.63) v3(115.96,198.74) v3(115.96,112.51) v3(115.96,111.62) v3(115.96,110.73) v3(115.96,109.84) v3(115.96,108.95) v3(115.96,25.26) v3(115.96,24.37) v3(115.96,23.48) v3(115.96,22.59) v3(115.96,21.7)
